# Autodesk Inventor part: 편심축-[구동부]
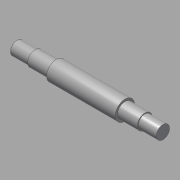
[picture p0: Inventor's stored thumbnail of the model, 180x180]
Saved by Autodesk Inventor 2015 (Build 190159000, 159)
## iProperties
Created: 2015-10
Part Number: 편심축-[구동부]
Document SubType Name: Modeling
Designer: mdu
Density: 7.86 g/cm^3
Material: 강철, 연강
Mass: 1163.82 g
Surface Area: 210.981 cm^2
Volume: 148.069 cm^3
Appearance: 강철
Author: mdu
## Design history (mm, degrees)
sketch "스케치1"
  geometry: L1 (-20.5, -41.331)-(-20.5, 32.669) reference; L2 (7.5, -30.031)-(7.5, 21.369) reference; L3 (135.5, -30.331)-(135.5, 21.669) reference; L4 (121.5, 21.369)-(121.5, -30.031) reference; L5 (184.5, -4.331)-(-7.5, -4.331); L6 (184.5, -4.331)-(184.5, 6.669); L7 (154.5, 8.169)-(121.5, 8.169); L8 (121.5, 8.169)-(121.5, 11.669); L9 (121.5, 11.669)-(7.5, 11.669); L10 (7.5, 11.669)-(7.5, 8.169); L11 (7.5, 8.169)-(-7.5, 8.169); L12 (-7.5, 8.169)-(-7.5, -4.331); L13 (154.5, 8.169)-(154.5, 6.669); L14 (154.5, 6.669)-(184.5, 6.669); C1 r 32.5 at (64.5, -4.331) reference; 1 further point
  constraints: 21 end point, 8 perpendicular, 5 point on line, 1 collinear
  dimensions: "d1" = 25 diameter of L11 L5; "d2" = 32 diameter of L9 L5; "d4" = 15 distance of L10.end L11.end; "d15" = 33 distance of L7.start L7.end; "d26" = 30 distance of L13.end L6.end; "d36" = 22 diameter of L14 L5
revolve "회전1" sketch "스케치1" stored, may be unused: angle "d6" = 90 deg
node "작업 평면1"
sketch "스케치2"
  geometry: C1 r 16 at (0, 0) reference; C2 r 20.75 at (0, 4)
  constraints: 1 centre point, 1 vertical alignment
  dimensions: "d34" = 4 distance of C2.centre C1.centre; "d35" = 41.5 diameter of C2
extrude "돌출1" join sketch "스케치2" stored distance "d9" = 40; taper "d10" = 0 deg
chamfer "모따기1" distance "d11" = 1; stored, may be unused: second distance "d12" = 2, angle "d13" = 45 deg
node "작업 평면2"
sketch "스케치3"
  geometry: L1 (-15, -10)-(-15, 10) reference; L2 (-15, 3)-(0, 3); L3 (0, -3)-(-15, -3); A1 r 3 centre (0, 0) between (0, -3) and (0, 3); 2 further points
  constraints: 4 end point, 2 perpendicular, 2 point on circle, 2 point on line, 2 tangent, 1 centre point, 1 horizontal alignment, 1 midpoint
  dimensions: "d16" = 18 dimension on A1 L1; "d17" = 6 distance between parallel lines of L3 L2
extrude "돌출2" cut sketch "스케치3" distance "d18" = 3.5; taper "d19" = 0 deg
node "솔리드1"
node "참조1"
node "참조2"
node "참조3"
node "참조4"
node "참조5"
other parameters: "d30" = 35
